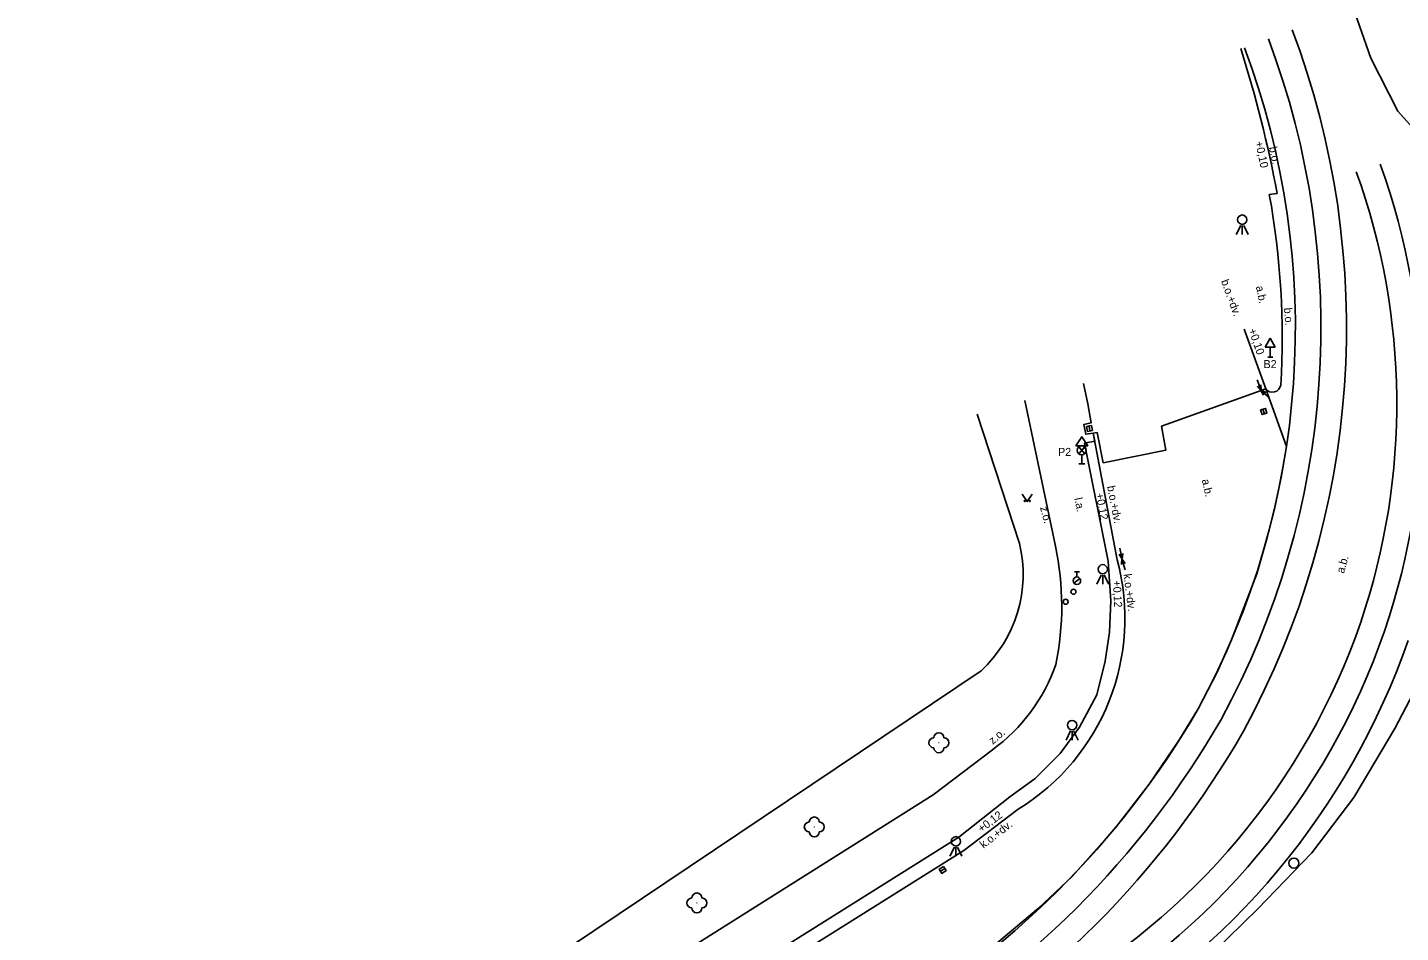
# Model space of a CAD drawing. Extents: x -598721 to -598598, y -1156938 to -1156772.
# Drawn here: x -598708.1 to -598639.4, y -1156881.3 to -1156836.1 of the extents above; entities that cross this region are included whole.
import ezdxf

# ---------------------------------------------------------------- set-up
doc = ezdxf.new("R2010")
doc.units = 0
for name, color, linetype in [('Vrstva 10', 7, 'Continuous'), ('Vrstva 13', 7, 'Continuous'), ('Vrstva 14', 7, 'Continuous'), ('Vrstva 19', 7, 'Continuous'), ('Vrstva 24', 7, 'Continuous'), ('Vrstva 25', 7, 'Continuous'), ('Vrstva 44', 7, 'Continuous'), ('Vrstva 49', 7, 'Continuous'), ('Vrstva 50', 7, 'Continuous'), ('Vrstva 63', 7, 'Continuous'), ('Vrstva 7', 7, 'Continuous')]:
    doc.layers.add(name, color=color, linetype=linetype)

msp = doc.modelspace()

# ---------------------------------------------------------------- linework, layer by layer
at = {"layer": 'Vrstva 10'}
for p, q in [((-598658.48, -1156861.89), (-598660.6, -1156855.43)), ((-598693.59, -1156890.53), (-598660.4, -1156868.25))]:
    msp.add_line(p, q, dxfattribs=at)
msp.add_arc((-598664.846, -1156863.438), 6.551, 312.7345, 13.66876, dxfattribs=at)
at = {"layer": 'Vrstva 13'}
for centre, radius, start, end in [((-598684.3, -1156851.077), 42.168, 331.38228, 20.65336), ((-598684.475, -1156851.099), 39.789, 331.38593, 20.59112), ((-598673.752, -1156854.889), 34.136, 341.32715, 19.82935), ((-598673.908, -1156854.609), 34.374, 299.14988, 340.96763), ((-598673.875, -1156854.607), 36.879, 299.48472, 340.80395), ((-598687.552, -1156848.072), 43.956, 299.6767, 329.84191), ((-598687.332, -1156848.349), 46.146, 299.91163, 330.21126)]:
    msp.add_arc(centre, radius, start, end, dxfattribs=at)
at = {"layer": 'Vrstva 14'}
msp.add_lwpolyline([(-598658.34, -1156859.415), (-598658.09, -1156859.79), (-598657.84, -1156859.415)], dxfattribs=at)
for centre, radius in [((-598658.215, -1156859.765), 0.025), ((-598657.965, -1156859.765), 0.025), ((-598662.51, -1156871.85), 0.00025), ((-598668.74, -1156876.06), 0.00025), ((-598674.61, -1156879.86), 0.00025)]:
    msp.add_circle(centre, radius, dxfattribs=at)
for centre, start, end in [((-598662.76, -1156871.85), 89.99999, 269.99999), ((-598662.51, -1156871.6), 0, 179.99999), ((-598662.26, -1156871.85), 270, 89.99999), ((-598662.51, -1156872.1), 179.99999, 359.99999), ((-598668.99, -1156876.06), 89.99999, 269.99999), ((-598668.74, -1156875.81), 0, 179.99999), ((-598668.49, -1156876.06), 270, 89.99999), ((-598668.74, -1156876.31), 179.99999, 359.99999), ((-598674.86, -1156879.86), 89.99999, 269.99999), ((-598674.61, -1156879.61), 0, 179.99999), ((-598674.36, -1156879.86), 270, 89.99999), ((-598674.61, -1156880.11), 179.99999, 359.99999)]:
    msp.add_arc(centre, 0.25, start, end, dxfattribs=at)
at = {"layer": 'Vrstva 19'}
for p, q in [((-598645.94, -1156851.62), (-598646.19, -1156852.07)), ((-598645.94, -1156851.62), (-598645.69, -1156852.07)), ((-598645.69, -1156852.07), (-598646.19, -1156852.07)), ((-598645.94, -1156852.07), (-598645.94, -1156852.57)), ((-598646.065, -1156852.57), (-598645.815, -1156852.57))]:
    msp.add_line(p, q, dxfattribs=at)
for centre, radius, start, end in [((-598684.388, -1156851.088), 40.979, 331.38299, 20.62273), ((-598673.697, -1156854.9), 35.347, 341.22758, 19.80298), ((-598673.891, -1156854.609), 35.626, 299.3215, 340.88454), ((-598687.439, -1156848.213), 45.047, 299.79577, 330.03181)]:
    msp.add_arc(centre, radius, start, end, dxfattribs=at)
at = {"layer": 'Vrstva 24'}
for p, q in [((-598655.735, -1156863.312), (-598655.485, -1156863.312)), ((-598655.61, -1156863.562), (-598655.61, -1156863.312)), ((-598655.757, -1156863.866), (-598655.462, -1156863.634))]:
    msp.add_line(p, q, dxfattribs=at)
for centre, radius in [((-598655.78, -1156864.3), 0.125), ((-598655.61, -1156863.75), 0.188), ((-598656.17, -1156864.8), 0.125)]:
    msp.add_circle(centre, radius, dxfattribs=at)
at = {"layer": 'Vrstva 25'}
for p, q in [((-598646.306, -1156855.17), (-598646.234, -1156855.41)), ((-598655.003, -1156856.017), (-598654.957, -1156856.263)), ((-598662.216, -1156878.141), (-598662.424, -1156878.279))]:
    msp.add_line(p, q, dxfattribs=at)
for points in [[(-598646.427, -1156855.207), (-598646.354, -1156855.446), (-598646.114, -1156855.374), (-598646.186, -1156855.134)], [(-598655.127, -1156856.041), (-598655.08, -1156856.286), (-598654.834, -1156856.239), (-598654.881, -1156855.994)], [(-598662.286, -1156878.036), (-598662.494, -1156878.174), (-598662.355, -1156878.383), (-598662.147, -1156878.245)]]:
    msp.add_lwpolyline(points, close=True, dxfattribs=at)
msp.add_circle((-598644.76, -1156877.87), 0.25, dxfattribs=at)
at = {"layer": 'Vrstva 44'}
for p, q in [((-598647.414, -1156845.993), (-598647.64, -1156846.445)), ((-598647.34, -1156845.995), (-598647.34, -1156846.445)), ((-598647.265, -1156845.993), (-598647.04, -1156846.445)), ((-598655.22, -1156857.06), (-598655.52, -1156857.404)), ((-598655.52, -1156857.06), (-598655.22, -1156857.404)), ((-598655.52, -1156857.91), (-598655.22, -1156857.91)), ((-598655.37, -1156857.91), (-598655.37, -1156857.46)), ((-598654.394, -1156863.473), (-598654.62, -1156863.925)), ((-598654.32, -1156863.475), (-598654.32, -1156863.925)), ((-598654.245, -1156863.473), (-598654.02, -1156863.925)), ((-598655.924, -1156871.263), (-598656.15, -1156871.715)), ((-598655.85, -1156871.265), (-598655.85, -1156871.715)), ((-598655.775, -1156871.263), (-598655.55, -1156871.715)), ((-598661.734, -1156877.073), (-598661.96, -1156877.525)), ((-598661.66, -1156877.075), (-598661.66, -1156877.525)), ((-598661.585, -1156877.073), (-598661.36, -1156877.525))]:
    msp.add_line(p, q, dxfattribs=at)
msp.add_lwpolyline([(-598655.67, -1156857.004), (-598655.07, -1156857.004), (-598655.37, -1156856.554), (-598655.67, -1156857.004)], dxfattribs=at)
for centre, radius in [((-598647.34, -1156845.7), 0.234), ((-598655.37, -1156857.232), 0.228), ((-598654.32, -1156863.18), 0.234), ((-598655.85, -1156870.97), 0.234), ((-598661.66, -1156876.78), 0.234)]:
    msp.add_circle(centre, radius, dxfattribs=at)
at = {"layer": 'Vrstva 49'}
for p, q in [((-598646.603, -1156853.711), (-598646.401, -1156854.238)), ((-598646.401, -1156854.238), (-598646.588, -1156854.026)), ((-598646.401, -1156854.238), (-598646.409, -1156853.955)), ((-598645.986, -1156854.607), (-598646.409, -1156854.235)), ((-598646.409, -1156854.235), (-598646.272, -1156854.481)), ((-598646.409, -1156854.235), (-598646.146, -1156854.336)), ((-598653.465, -1156862.115), (-598653.351, -1156862.667)), ((-598653.351, -1156862.667), (-598653.501, -1156862.427)), ((-598653.358, -1156862.661), (-598653.372, -1156862.943)), ((-598653.198, -1156863.202), (-598653.358, -1156862.661)), ((-598653.358, -1156862.661), (-598653.189, -1156862.887)), ((-598653.351, -1156862.667), (-598653.313, -1156862.387))]:
    msp.add_line(p, q, dxfattribs=at)
at = {"layer": 'Vrstva 63'}
for points in [[(-598708.08, -1156905.8), (-598661.52, -1156876.57), (-598658.97, -1156874.55), (-598657.7, -1156873.64), (-598656.44, -1156872.39), (-598655.48, -1156871.07), (-598654.62, -1156869.45), (-598654.19, -1156867.78), (-598653.98, -1156866.32), (-598653.91, -1156864.76), (-598654.05, -1156862.78), (-598655.23, -1156856.88), (-598654.715, -1156856.779), (-598654.79, -1156856.38), (-598654.593, -1156856.343), (-598654.29, -1156857.85), (-598651.17, -1156857.23), (-598651.38, -1156856.03), (-598646.17, -1156854.15), (-598645.13, -1156857.04), (-598645.4, -1156858.59), (-598645.73, -1156860.14), (-598646.11, -1156861.65), (-598646.62, -1156863.4), (-598647.88, -1156866.71), (-598648.6, -1156868.32), (-598649.546, -1156870.155), (-598650.51, -1156871.73), (-598652, -1156873.923), (-598653.7, -1156876.114), (-598655.85, -1156878.54), (-598657.53, -1156880.12), (-598660.25, -1156882.4)], [(-598648.81, -1156882.36), (-598646.56, -1156880.16), (-598643.86, -1156877.35), (-598641.77, -1156874.58), (-598639.72, -1156871.14), (-598637.35, -1156866.63)]]:
    msp.add_lwpolyline(points, dxfattribs=at)
at = {"layer": 'Vrstva 7'}
for p, q in [((-598645.99, -1156844.44), (-598645.6, -1156844.4)), ((-598646.17, -1156854.15), (-598647.25, -1156851.17)), ((-598658.21, -1156854.74), (-598656.68, -1156862.03))]:
    msp.add_line(p, q, dxfattribs=at)
for points in [[(-598636.72, -1156847), (-598638.68, -1156841.26), (-598639.57, -1156840.28), (-598640.91, -1156837.62), (-598647.32, -1156819.37), (-598657.11, -1156791.6), (-598660.49, -1156782.01)], [(-598655.28, -1156853.89), (-598655.07, -1156854.91), (-598654.89, -1156855.85), (-598655.26, -1156855.94), (-598655.17, -1156856.43), (-598654.79, -1156856.38), (-598653.6, -1156862.71)], [(-598659.83, -1156872.2), (-598662.79, -1156874.45), (-598677.32, -1156883.6), (-598696.01, -1156895.4)], [(-598658.54, -1156875.17), (-598661.27, -1156877.23), (-598674.96, -1156885.84), (-598707.02, -1156905.99)]]:
    msp.add_lwpolyline(points, dxfattribs=at)
for centre, radius, start, end in [((-598701.722, -1156854.635), 57.047, 10.33558, 17.84845), ((-598684.763, -1156851.541), 39.418, 356.46724, 10.37845), ((-598645.831, -1156853.911), 0.415, 215.14485, 351.84661), ((-598670.914, -1156865.033), 14.547, 348.47374, 11.91405), ((-598664.394, -1156865.64), 11.185, 301.56073, 15.18572), ((-598665.04, -1156865.013), 8.877, 305.94245, 340.74936)]:
    msp.add_arc(centre, radius, start, end, dxfattribs=at)

# ---------------------------------------------------------------- texts
at = {"layer": 'Vrstva 49'}
for s, rotation, p in [('b.o.', 281.73352, (-598646.008, -1156842.089)), ('b.o.+dv.', 290.01079, (-598648.41, -1156848.77)), ('a.b.', 282.03892, (-598646.665, -1156849.05)), ('b.o.', 274.5092, (-598645.256, -1156850.113)), ('a.b.', 282.37216, (-598649.367, -1156858.712)), ('b.o.+dv.', 281.03817, (-598654.104, -1156859.038)), ('z.o.', 284.78445, (-598657.457, -1156860.09)), ('l.a.', 282.03892, (-598655.742, -1156859.637)), ('a.b.', 73.68615, (-598642.265, -1156863.408)), ('k.o.+dv.', 277.11226, (-598653.282, -1156863.428)), ('z.o.', 40.63194, (-598659.813, -1156871.956)), ('k.o.+dv.', 37.69148, (-598660.279, -1156877.153))]:
    msp.add_text(s, height=0.4, rotation=rotation, dxfattribs=at).set_placement(p)
for s, p in [('B2', (-598646.278, -1156853.12)), ('P2', (-598656.55, -1156857.51))]:
    msp.add_text(s, height=0.4, dxfattribs=at).set_placement(p)
at = {"layer": 'Vrstva 50'}
for s, rotation, p in [('+0,10', 282.14151, (-598646.699, -1156841.822)), ('+0,10', 289.08096, (-598647.034, -1156851.215)), ('+0,12', 280.22301, (-598654.671, -1156859.406)), ('+0,12', 273.00297, (-598653.812, -1156863.748)), ('+0,12', 36.78806, (-598660.378, -1156876.358))]:
    msp.add_text(s, height=0.4, rotation=rotation, dxfattribs=at).set_placement(p)

doc.saveas('drawing.dxf')
